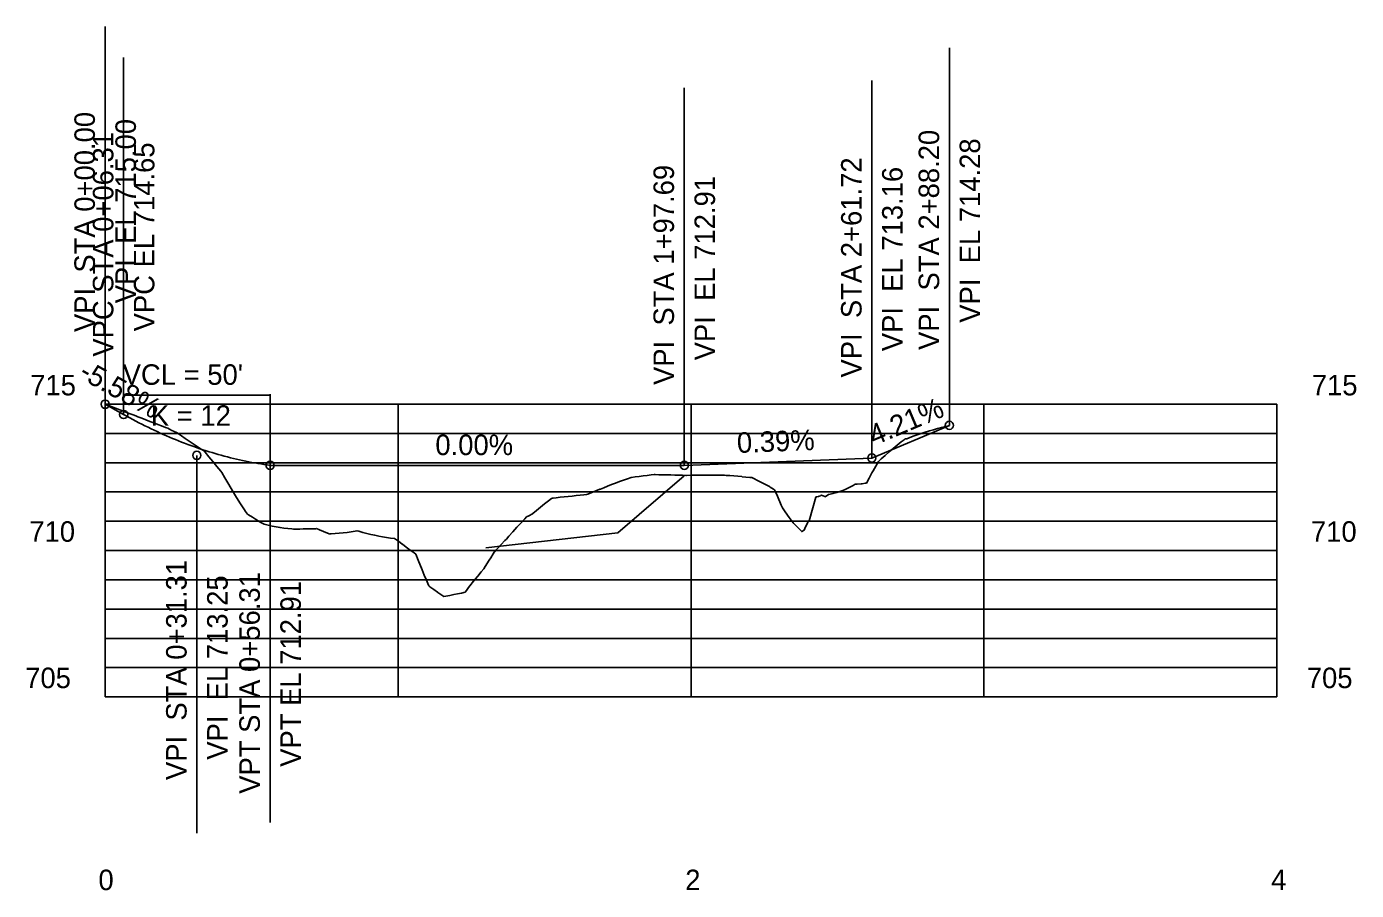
# Model space of a CAD drawing. Extents: x 564505 to 632085, y 226062 to 275176.
# Drawn here: x 564505 to 564959, y 274881 to 275176 of the extents above; entities that cross this region are included whole.
import ezdxf

# ---------------------------------------------------------------- set-up
doc = ezdxf.new("R2010")
doc.units = 0
for name, color, linetype in [('E_PROF_Grid', 7, 'Continuous'), ('E_PROF_GridMin', 7, 'Continuous'), ('P_DRN_Pipes', 7, 'Continuous'), ('P_MISC_TXT', 7, 'Continuous'), ('P_PROF', 7, 'Continuous'), ('P_PROF_Data', 7, 'Continuous'), ('P_PROF_Grades', 7, 'Continuous'), ('P_PROF_VPINotes', 7, 'Continuous')]:
    doc.layers.add(name, color=color, linetype=linetype)

msp = doc.modelspace()

# ---------------------------------------------------------------- linework, layer by layer
at = {"layer": 'E_PROF_Grid'}
for p, q in [((564531.85, 275047.06), (564931.85, 275047.06)), ((564531.85, 275047.06), (564931.85, 275047.06)), ((564731.85, 274947.06), (564731.85, 275047.06)), ((564531.85, 274997.06), (564931.85, 274997.06))]:
    msp.add_line(p, q, dxfattribs=at)
at = {"layer": 'E_PROF_GridMin'}
for p, q in [((564631.85, 274947.06), (564631.85, 275047.06)), ((564831.85, 274947.06), (564831.85, 275047.06)), ((564531.85, 275037.06), (564931.85, 275037.06)), ((564531.85, 275027.06), (564931.85, 275027.06)), ((564531.85, 275017.06), (564931.85, 275017.06)), ((564531.85, 275007.06), (564931.85, 275007.06)), ((564531.85, 274987.06), (564931.85, 274987.06)), ((564531.85, 274977.06), (564931.85, 274977.06)), ((564531.85, 274967.06), (564931.85, 274967.06)), ((564531.85, 274957.06), (564931.85, 274957.06))]:
    msp.add_line(p, q, dxfattribs=at)
at = {"layer": 'P_DRN_Pipes'}
for p, q in [((564706.85, 275003.06), (564729.54, 275022.56)), ((564661.85, 274997.96), (564706.85, 275003.06))]:
    msp.add_line(p, q, dxfattribs=at)
at = {"layer": 'P_MISC_TXT'}
msp.add_lwpolyline([(564531.85, 275047.04), (564540.36, 275043.79), (564541.71, 275043.28), (564542.56, 275042.95), (564543.05, 275042.76), (564544.4, 275042.23), (564545.74, 275041.7), (564547.09, 275041.17), (564548.44, 275040.65), (564549.78, 275040.13), (564551.13, 275039.61), (564552.47, 275039.1), (564553.23, 275038.82), (564553.82, 275038.48), (564554.6, 275038.05), (564555.16, 275037.79), (564556.38, 275037.25), (564556.51, 275037.16), (564557.86, 275036.24), (564559.2, 275035.32), (564560.55, 275034.42), (564561.89, 275033.51), (564563.24, 275032.62), (564564.59, 275031.72), (564565.73, 275030.96), (564565.94, 275030.71), (564567.28, 275029.08), (564568.63, 275027.44), (564569.98, 275025.79), (564571.33, 275024.13), (564571.66, 275023.72), (564572.67, 275021.95), (564574.02, 275019.64), (564575.37, 275017.4), (564576.72, 275015.2), (564578.06, 275013.07), (564579.41, 275011), (564579.79, 275010.44), (564580.46, 275009.46), (564580.76, 275009.26), (564582.11, 275008.42), (564583.23, 275007.76), (564583.45, 275007.62), (564584.8, 275006.8), (564585.85, 275006.2), (564586.15, 275006.11), (564587.5, 275005.76), (564588.84, 275005.44), (564590.19, 275005.16), (564591.54, 275004.92), (564592.89, 275004.71), (564594.23, 275004.55), (564595.58, 275004.42), (564596.1, 275004.38), (564596.93, 275004.38), (564598.28, 275004.41), (564599.39, 275004.48), (564599.62, 275004.46), (564600.97, 275004.42), (564602.32, 275004.44), (564603.67, 275004.51), (564604.01, 275004.54), (564605.01, 275004.09), (564606.36, 275003.51), (564607.71, 275002.97), (564608.05, 275002.85), (564608.35, 275002.7), (564608.4, 275002.71), (564609.06, 275002.74), (564610.4, 275002.84), (564611.75, 275002.96), (564613.1, 275003.1), (564614.45, 275003.27), (564615.79, 275003.46), (564617.14, 275003.68), (564617.87, 275003.81), (564618.49, 275003.63), (564619.84, 275003.26), (564621.18, 275002.91), (564622.53, 275002.58), (564623.88, 275002.28), (564625.23, 275002), (564626.57, 275001.76), (564627.92, 275001.53), (564629.27, 275001.33), (564630.62, 275001.16), (564630.67, 275001.16), (564631.96, 275000.22), (564633.27, 274999.28), (564633.31, 274999.24), (564634.66, 274998.23), (564636.01, 274997.22), (564637.35, 274996.22), (564637.85, 274995.86), (564638.7, 274993.8), (564640.05, 274990.51), (564640.79, 274988.7), (564641.39, 274987.2), (564642.29, 274984.99), (564642.74, 274984.66), (564644.09, 274983.71), (564645.28, 274982.88), (564645.44, 274982.76), (564646.78, 274981.78), (564647.42, 274981.32), (564648.13, 274981.46), (564649.48, 274981.74), (564650.83, 274982.02), (564650.93, 274982.04), (564652.17, 274982.28), (564653.52, 274982.55), (564654.75, 274982.8), (564654.87, 274982.98), (564656.22, 274984.91), (564656.32, 274985.06), (564657.56, 274986.55), (564658.91, 274988.16), (564659.03, 274988.3), (564660.26, 274989.82), (564661.08, 274990.83), (564661.61, 274991.66), (564662.95, 274993.76), (564663.46, 274994.54), (564664.3, 274995.93), (564664.68, 274996.54), (564665.28, 274997.31), (564665.65, 274997.69), (564667, 274999.07), (564668.34, 275000.44), (564668.8, 275000.9), (564669.69, 275001.95), (564671.04, 275003.5), (564672.39, 275005), (564673.73, 275006.46), (564675.08, 275007.87), (564675.72, 275008.53), (564676.43, 275008.92), (564677.78, 275009.65), (564677.87, 275009.7), (564679.12, 275010.76), (564680.47, 275011.88), (564681.82, 275012.97), (564683.17, 275014.04), (564684.22, 275014.86), (564684.51, 275014.92), (564684.81, 275014.98), (564685.86, 275015.1), (564687.21, 275015.25), (564688.56, 275015.39), (564689.9, 275015.53), (564691.25, 275015.67), (564692.6, 275015.81), (564693.95, 275015.95), (564695.29, 275016.09), (564696.18, 275016.18), (564696.64, 275016.37), (564697.99, 275016.92), (564699.34, 275017.45), (564700.68, 275017.98), (564700.9, 275018.06), (564702.03, 275018.53), (564703.38, 275019.07), (564704.73, 275019.6), (564706.07, 275020.11), (564707.42, 275020.61), (564708.77, 275021.1), (564710.12, 275021.57), (564711.46, 275022.02), (564711.57, 275022.05), (564712.81, 275022.22), (564714.16, 275022.39), (564715.51, 275022.56), (564716.85, 275022.72), (564718.2, 275022.87), (564719.3, 275023), (564719.55, 275022.99), (564720.9, 275022.97), (564722.24, 275022.94), (564723.59, 275022.9), (564724.94, 275022.87), (564726.29, 275022.83), (564727.58, 275022.79), (564727.63, 275022.79), (564727.63, 275022.79), (564728.98, 275022.76), (564730.08, 275022.73), (564730.33, 275022.74), (564731.68, 275022.77), (564733.02, 275022.79), (564734.37, 275022.8), (564735.72, 275022.81), (564737.07, 275022.82), (564738.41, 275022.82), (564739.76, 275022.82), (564741.11, 275022.81), (564742.46, 275022.79), (564743.3, 275022.78), (564743.8, 275022.74), (564745.15, 275022.64), (564746.5, 275022.53), (564747.85, 275022.42), (564749.19, 275022.3), (564749.27, 275022.29), (564750.54, 275022.17), (564751.89, 275022.04), (564752.66, 275021.96), (564753.24, 275021.68), (564754.58, 275021.02), (564755.93, 275020.33), (564757.28, 275019.62), (564758.63, 275018.89), (564758.85, 275018.76), (564759.97, 275018.02), (564760.33, 275017.79), (564760.64, 275017.14), (564761.32, 275015.61), (564762.67, 275012.58), (564763.08, 275011.66), (564764.02, 275010.32), (564765.36, 275008.38), (564766.66, 275006.5), (564766.68, 275006.48), (564766.71, 275006.45), (564766.79, 275006.37), (564768.06, 275005.13), (564769.41, 275003.79), (564769.65, 275003.54), (564770.49, 275004.05), (564770.75, 275004.62), (564771.75, 275006.7), (564772.1, 275007.05), (564772.22, 275007.16), (564773.45, 275011.64), (564774.46, 275015.31), (564774.56, 275015.41), (564774.82, 275015.45), (564775.42, 275015.56), (564775.6, 275015.64), (564776, 275015.77), (564776.19, 275015.84), (564776.44, 275015.93), (564777.56, 275015.49), (564777.67, 275015.45), (564778.79, 275016.18), (564778.93, 275016.21), (564780.3, 275016.52), (564781.67, 275016.89), (564783.04, 275017.33), (564783.1, 275017.35), (564784.41, 275017.92), (564785.78, 275018.58), (564787.16, 275019.3), (564787.89, 275019.72), (564788.53, 275019.75), (564789.9, 275019.84), (564790.28, 275019.87), (564791.27, 275020.02), (564791.71, 275020.09), (564792.64, 275021.82), (564793.61, 275023.62), (564794.01, 275024.32), (564795.38, 275026.73), (564795.82, 275027.49), (564796.75, 275028.35), (564798.12, 275029.57), (564799.49, 275030.77), (564800.86, 275031.94), (564802.23, 275033.07), (564803.6, 275034.17), (564804.26, 275034.68), (564804.59, 275034.9), (564804.81, 275035.13), (564804.97, 275035.17), (564805.48, 275035.27), (564806.34, 275035.59), (564807.71, 275036.08), (564809.08, 275036.56), (564810.45, 275037.03), (564811.82, 275037.47), (564813.2, 275037.91), (564814.57, 275038.32), (564815.94, 275038.72), (564817.31, 275039.1), (564818.68, 275039.47), (564820.05, 275039.81)], dxfattribs=at)
at = {"layer": 'P_PROF'}
for p, q in [((564531.85, 275047.04), (564538.16, 275043.52)), ((564793.57, 275028.66), (564820.05, 275039.81)), ((564729.54, 275026.16), (564793.57, 275028.66)), ((564588.16, 275026.16), (564729.54, 275026.16))]:
    msp.add_line(p, q, dxfattribs=at)
msp.add_lwpolyline([(564538.16, 275043.52), (564539.2, 275042.94), (564540.24, 275042.37), (564541.28, 275041.81), (564542.32, 275041.26), (564543.36, 275040.72), (564544.41, 275040.19), (564545.45, 275039.67), (564546.49, 275039.16), (564547.53, 275038.65), (564548.57, 275038.16), (564549.61, 275037.67), (564550.66, 275037.2), (564551.7, 275036.73), (564552.74, 275036.27), (564553.78, 275035.82), (564554.82, 275035.38), (564555.86, 275034.95), (564556.91, 275034.53), (564557.95, 275034.12), (564558.99, 275033.72), (564560.03, 275033.32), (564561.07, 275032.94), (564562.11, 275032.56), (564564.2, 275031.84), (564565.24, 275031.49), (564566.28, 275031.16), (564567.32, 275030.83), (564568.36, 275030.51), (564569.41, 275030.19), (564570.45, 275029.89), (564571.49, 275029.6), (564572.53, 275029.32), (564573.57, 275029.04), (564574.61, 275028.78), (564575.66, 275028.52), (564576.7, 275028.27), (564577.74, 275028.03), (564578.78, 275027.81), (564579.82, 275027.59), (564580.86, 275027.38), (564581.91, 275027.17), (564582.95, 275026.98), (564583.99, 275026.8), (564585.03, 275026.63), (564586.07, 275026.46), (564587.11, 275026.31), (564588.16, 275026.16)], dxfattribs=at)
at = {"layer": 'P_PROF_Data'}
for p, q in [((564531.85, 274947.06), (564531.85, 275047.06)), ((564531.85, 275047.06), (564541.85, 275047.06)), ((564531.85, 275047.06), (564541.85, 275047.06)), ((564931.85, 275047.06), (564921.85, 275047.06)), ((564931.85, 275047.06), (564921.85, 275047.06)), ((564931.85, 274947.06), (564931.85, 275047.06)), ((564531.85, 274997.06), (564541.85, 274997.06)), ((564931.85, 274997.06), (564921.85, 274997.06)), ((564531.85, 274947.06), (564531.85, 274957.06)), ((564731.85, 274947.06), (564731.85, 274957.06)), ((564931.85, 274947.06), (564931.85, 274957.06)), ((564631.85, 274947.06), (564631.85, 274952.06)), ((564831.85, 274947.06), (564831.85, 274952.06)), ((564531.85, 274947.06), (564931.85, 274947.06)), ((564531.85, 274947.06), (564541.85, 274947.06)), ((564931.85, 274947.06), (564921.85, 274947.06))]:
    msp.add_line(p, q, dxfattribs=at)
at = {"layer": 'P_PROF_VPINotes'}
for p, q in [((564531.85, 275057.04), (564531.85, 275176.04)), ((564820.05, 275049.81), (564820.05, 275168.81)), ((564538.16, 275053.52), (564538.16, 275165.52)), ((564729.54, 275036.16), (564729.54, 275155.16)), ((564793.57, 275038.66), (564793.57, 275157.66)), ((564531.85, 275047.04), (564531.85, 275057.04)), ((564538.16, 275043.52), (564538.16, 275053.52)), ((564538.16, 275043.52), (564538.16, 275050.52)), ((564588.16, 275026.16), (564588.16, 275050.52)), ((564820.05, 275039.81), (564820.05, 275049.81)), ((564793.57, 275028.66), (564793.57, 275038.66)), ((564729.54, 275026.16), (564729.54, 275036.16)), ((564563.16, 275029.56), (564563.16, 275019.56)), ((564588.16, 275026.16), (564588.16, 275016.16)), ((564563.16, 275019.56), (564563.16, 274900.56)), ((564588.16, 275016.16), (564588.16, 274904.16))]:
    msp.add_line(p, q, dxfattribs=at)
msp.add_lwpolyline([(564538.16, 275050.17), (564588.16, 275050.17)], dxfattribs=at)
for centre in [(564531.85, 275047.04), (564538.16, 275043.52), (564820.05, 275039.81), (564563.16, 275029.56), (564793.57, 275028.66), (564588.16, 275026.16), (564729.54, 275026.16)]:
    msp.add_circle(centre, 1.4, dxfattribs=at)

# ---------------------------------------------------------------- texts
at = {"layer": 'P_PROF_Grades'}
for s, height, p in [('715', 7, (564506.26, 275050.06)), ('715', 7, (564506.26, 275050.06)), ('715', 7, (564943.76, 275050.06)), ('715', 7, (564943.76, 275050.06)), ('710', 7, (564505.96, 275000.06)), ('710', 7, (564943.46, 275000.06)), ('705', 7, (564504.55, 274950.06)), ('705', 7, (564942.05, 274950.06)), ('-', 0.0001, (564531.85, 274947.06)), ('0', 7, (564529.56, 274881.06)), ('2', 7, (564729.86, 274881.06)), ('4', 7, (564929.86, 274881.06))]:
    msp.add_text(s, height=height, dxfattribs=at).set_placement(p)
at = {"layer": 'P_PROF_VPINotes'}
for s, rotation, p in [('VPI  STA 0+00.00', 90, (564528.35, 275071.7)), ('VPI  EL 715.00', 90, (564542.35, 275081.51)), ('VPC STA 0+06.31', 90, (564534.66, 275063.28)), ('VPI  STA 2+88.20', 90, (564816.55, 275065.58)), ('VPI  EL 714.28', 90, (564830.55, 275074.87)), ('VPC EL 714.65', 90, (564548.66, 275071.93)), ('VPI  STA 1+97.69', 90, (564726.04, 275053.61)), ('VPI  STA 2+61.72', 90, (564790.07, 275056.16)), ('VPI  EL 713.16', 90, (564804.07, 275065.15)), ('VPI  EL 712.91', 90, (564740.04, 275062.04)), ('-5.58%', 330.8242, (564522.46, 275056.29)), ('4.21%', 22.8421, (564794.38, 275032.8)), ('0.00%', 360, (564644.57, 275029.66)), ('0.39%', 2.2359, (564747.65, 275030.37)), ('VPI  STA 0+31.31', 90, (564559.66, 274918.67)), ('VPI  EL 713.25', 90, (564573.66, 274925.61)), ('VPT STA 0+56.31', 90, (564584.66, 274913.97)), ('VPT EL 712.91', 90, (564598.66, 274923.18))]:
    msp.add_text(s, height=7, rotation=rotation, dxfattribs=at).set_placement(p)
for s, p in [("VCL = 50'", (564537.83, 275053.67)), ('K = 12', (564547.45, 275039.67))]:
    msp.add_text(s, height=7, dxfattribs=at).set_placement(p)

doc.saveas('drawing.dxf')
